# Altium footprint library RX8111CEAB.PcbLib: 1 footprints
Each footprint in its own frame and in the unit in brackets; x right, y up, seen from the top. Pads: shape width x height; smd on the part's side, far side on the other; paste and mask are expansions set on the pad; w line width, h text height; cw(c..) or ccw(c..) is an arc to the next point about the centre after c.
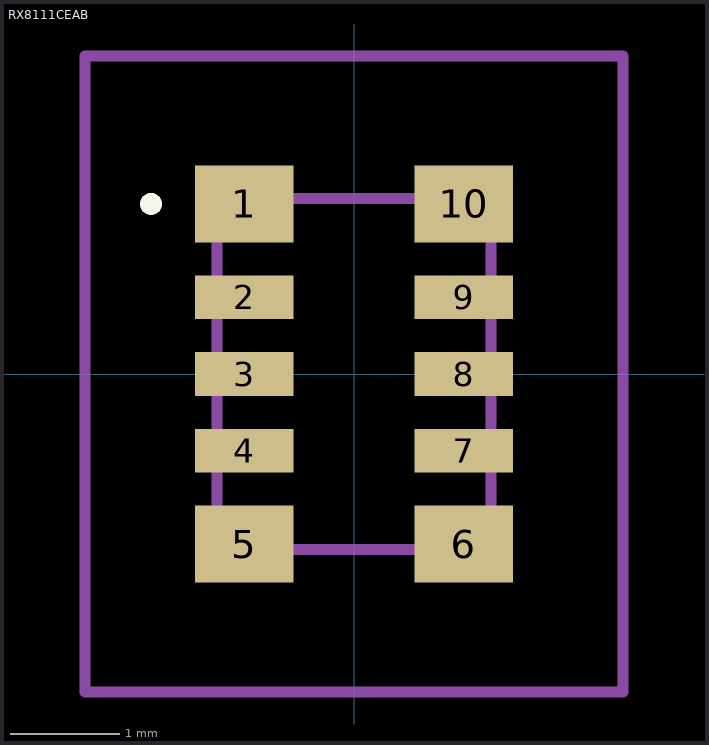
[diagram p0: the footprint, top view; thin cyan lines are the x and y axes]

## RX8111CEAB [mm]
pads (10):
  rect 0.9x0.7 smd: 1(-1,1.55) 5(-1,-1.55) 6(1,-1.55) 10(1,1.55)
  rect 0.9x0.4 smd: 2(-1,0.7) 3(-1,0) 4(-1,-0.7) 7(1,-0.7) 8(1,0) 9(1,0.7)
Top Overlay:
  lines w0.1: -1.9,1.55 cw(c-1.85,1.55) -1.8,1.55 ; -1.9,1.55 -1.9,1.55 ; -1.9,1.55 ccw(c-1.85,1.55) -1.8,1.55 ; -1.8,1.55 -1.8,1.55
Mechanical 15:
  lines w0.1: -1.25,-1.6 1.25,-1.6 1.25,1.6 -1.25,1.6 -1.25,-1.6
Mechanical 20:
  lines w0.1: -2.45,-2.9 2.45,-2.9 2.45,2.9 -2.45,2.9 -2.45,-2.9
